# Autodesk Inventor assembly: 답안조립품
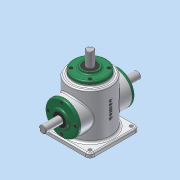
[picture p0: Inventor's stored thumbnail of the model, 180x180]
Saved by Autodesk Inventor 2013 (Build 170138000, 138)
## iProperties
Created: 2015-10
Part Number: 답안조립품
Document SubType Name: Assembly
Designer: Administrator
Author: Administrator
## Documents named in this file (18)
- C:\Users\Administrator\Desktop\451008V1015\답안조립품.iam
- C:\Users\Administrator\Desktop\451008V1015\1본체.ipt
- C:\Users\Administrator\Desktop\451008V1015\커버.ipt
- C:\Users\Administrator\Desktop\451008V1015\M4.ipt
- C:\Users\Administrator\Desktop\451008V1015\베어링 6203.ipt
- C:\Users\Administrator\Desktop\451008V1015\오일실.ipt
- C:\Users\Administrator\Desktop\451008V1015\메인 축.ipt
- 메인 축.ipt
- C:\Users\Administrator\Desktop\451008V1015\서브 축.ipt
- 서브 축.ipt
- C:\Users\Administrator\Desktop\451008V1015\키 5x5.ipt
- C:\Users\Administrator\Desktop\451008V1015\키 4x4.ipt
- C:\Users\Administrator\Desktop\451008V1015\메인 베벨기어.ipt
- C:\Users\Administrator\Desktop\451008V1015\서브 베벨기어.ipt
- C:\Users\Administrator\Desktop\451008V1015\커버_MIR.ipt
- C:\Users\Administrator\Desktop\451008V1015\메인 축_MIR.ipt
- C:\Users\Administrator\Desktop\451008V1015\키 5x5_MIR.ipt
- C:\Users\Administrator\Desktop\451008V1015\메인 베벨기어_MIR.ipt
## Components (13 placed, 2 different names)
1. 1본체:1
2. M4:1
3. M4:2
4. M4:3
5. M4:4
6. M4:5
7. M4:6
8. M4:7
9. M4:8
10. M4:9
11. M4:10
12. M4:11
13. M4:12
